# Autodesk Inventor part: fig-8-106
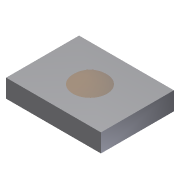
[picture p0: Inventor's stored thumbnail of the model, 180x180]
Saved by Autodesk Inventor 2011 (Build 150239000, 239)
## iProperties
Created: 2009-09
Part Number: fig-8-106
Document SubType Name: Modeling
Designer: Sham
Density: 1 g/cm^3
Author: Sham
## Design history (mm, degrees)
sketch "Sketch1"
  geometry: L1 (-26, 20)-(0, 20); L2 (0, 20)-(0, 0); L3 (0, 0)-(-26, 0); L4 (-26, 0)-(-26, 20)
  constraints: 8 end point, 2 parallel, 1 horizontal, 1 perpendicular
extrude "Extrusion1" new body sketch "Sketch1" distance "d0" = 5; taper "d1" = 0 deg
workplane "Work Plane1"
sketch "Sketch2"
  geometry: L1 (13, 8)-(13, 5); A1 r 7.517 centre (12.377, -0.349) between (17.658, 5) and (13, 7.142)
  constraints: 2 end point, 2 point on circle, 1 centre point
feature "RevolutionSrf2" sketch "Sketch2" dims angle "d4" = 90 deg
body "Solid1"
body "Srf2"
